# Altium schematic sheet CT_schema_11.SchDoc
size 281 x 153 mm
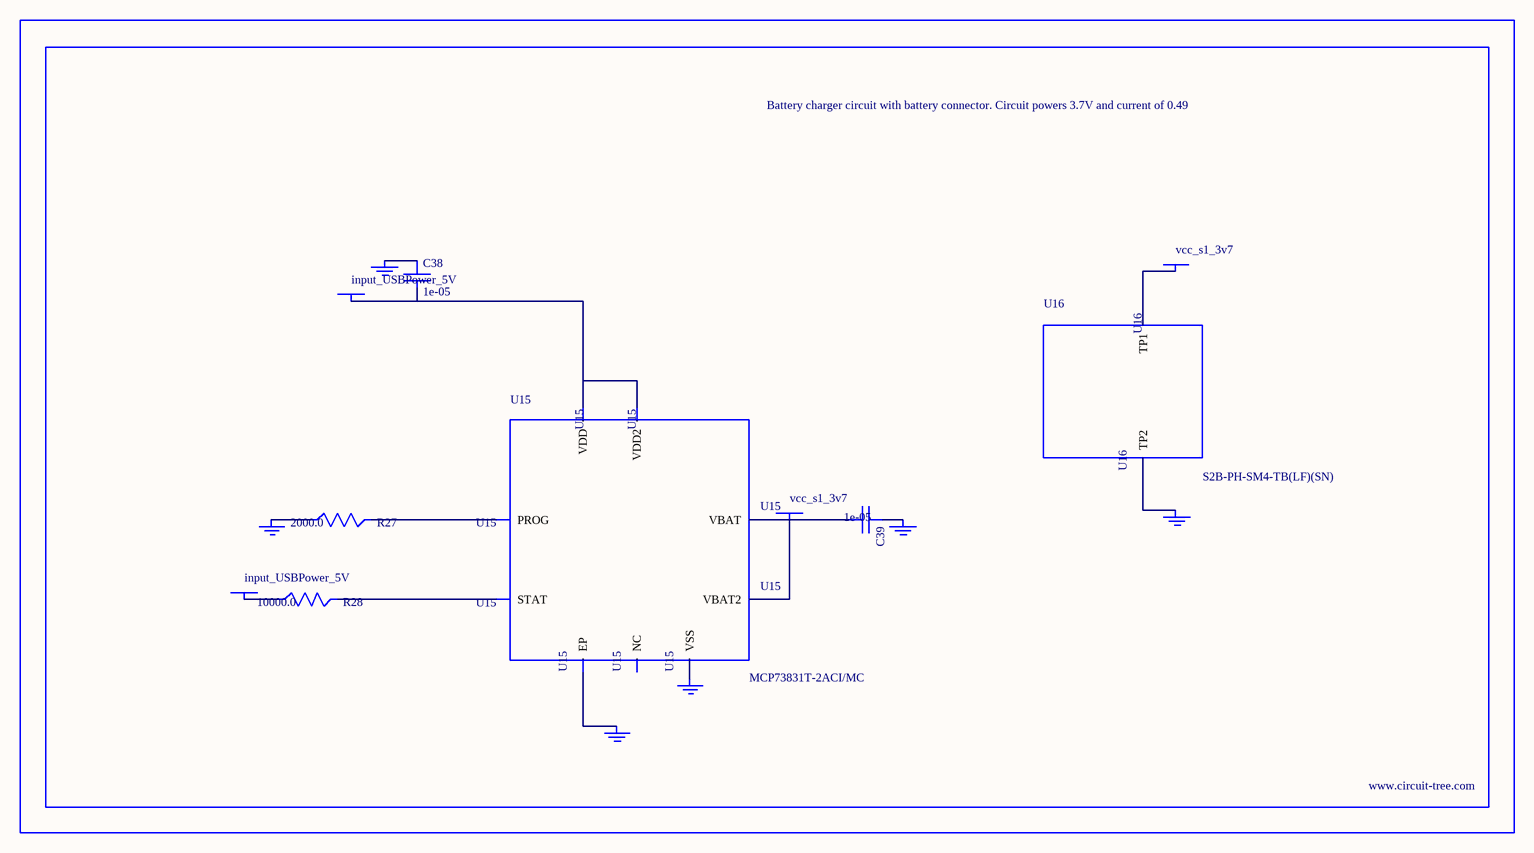
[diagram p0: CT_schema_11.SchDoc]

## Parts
BORDER10  (no value)
C38  1e-05  [C1206]
C39  1e-05  [C1206]
GND_INSTANCE_10_0  (no value)
GND_INSTANCE_10_1  (no value)
GND_INSTANCE_10_2  (no value)
GND_INSTANCE_10_3  (no value)
GND_INSTANCE_10_4  (no value)
GND_INSTANCE_10_5  (no value)
POWER_INSTANCE_10_0  input_USBPower_5V
POWER_INSTANCE_10_1  input_USBPower_5V
POWER_INSTANCE_10_2  vcc_s1_3v7
POWER_INSTANCE_10_3  vcc_s1_3v7
R27  2000.0  [R0603]
R28  10000.0  [R0603]
U15  MCP73831T-2ACI/MC  [DFN8_2X3MC]
U16  S2B-PH-SM4-TB(LF)(SN)  [JST-2-SMD]

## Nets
NetC38_1: C38.1 GND_INSTANCE_10_0.0(GND)
NetC38_2: C38.2 POWER_INSTANCE_10_0.0(PWR) U15.1(VDD) U15.2(VDD2)
NetC39_1: C39.1 GND_INSTANCE_10_1.0(GND)
NetC39_2: C39.2 POWER_INSTANCE_10_2.0(PWR) U15.3(VBAT) U15.4(VBAT2)
NetGND_INSTANCE_10_2_0: GND_INSTANCE_10_2.0(GND) R27.1
NetGND_INSTANCE_10_3_0: GND_INSTANCE_10_3.0(GND) U15.9(EP)
NetGND_INSTANCE_10_4_0: GND_INSTANCE_10_4.0(GND) U15.6(VSS)
NetGND_INSTANCE_10_5_0: GND_INSTANCE_10_5.0(GND) U16.2(TP2)
NetPOWER_INSTANCE_10_1_0: POWER_INSTANCE_10_1.0(PWR) R28.1
NetPOWER_INSTANCE_10_3_0: POWER_INSTANCE_10_3.0(PWR) U16.1(TP1)
NetR27_2: R27.2 U15.8(PROG)
NetR28_2: R28.2 U15.5(STAT)

Not connected (* = marked no-connect by the designer): U15 7(NC)

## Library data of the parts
BORDER10 = BORDER_PAGE10
C38 C39 = C1206C106K3RACTU
GND_INSTANCE_10_0-GND_INSTANCE_10_5 = GND
POWER_INSTANCE_10_0-POWER_INSTANCE_10_3 = PWR
R27 = RC0603JR-072KL
R28 = RC0603JR-0710KL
